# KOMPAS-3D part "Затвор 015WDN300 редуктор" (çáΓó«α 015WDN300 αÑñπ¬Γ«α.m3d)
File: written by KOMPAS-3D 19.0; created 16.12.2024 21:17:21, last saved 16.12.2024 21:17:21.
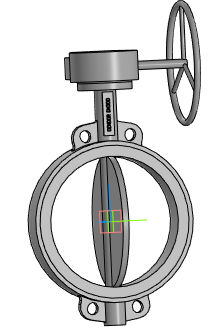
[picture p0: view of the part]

Document properties: Автор: Евгений; Полное имя файла: ..\..\Затворы\1.1 Тип 015W. Затвор дисковый поворотный Межфланцевый\Затворы дополнение\Затвор 015WDN50.a3d

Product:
- Part/product: Затвор 015WDN300 редуктор
    Масса: 51.6031

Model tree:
1. Операция без истории:1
